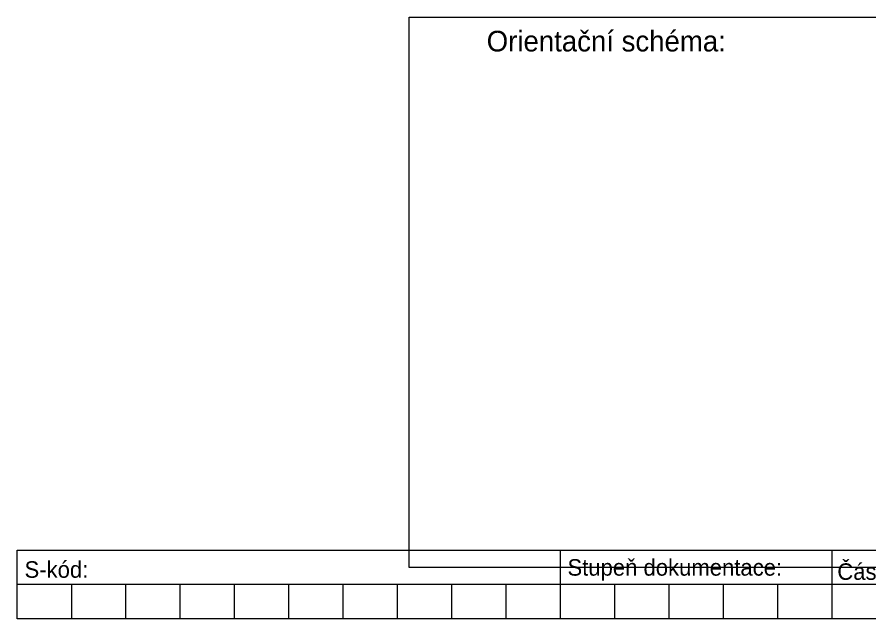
# Model space of a CAD drawing. Extents: x 3181 to 4881, y -2428 to -1984.
# Drawn here: x 3181 to 3800, y -2428 to -1991 of the extents above; entities that cross this region are included whole.
import ezdxf

# ---------------------------------------------------------------- set-up
doc = ezdxf.new("R2010")
doc.units = 0
doc.layers.add('Vrstva 2', color=7, linetype='Continuous')
doc.layers.add('Vrstva 8', color=7, linetype='Continuous')

# ---------------------------------------------------------------- blocks, each defined once
blk = doc.blocks.new('_U1')
at = {"layer": 'Vrstva 8'}
for p, q in [((-4.55, 0.25), (-4.55, -0.25)), ((-2.575, 0.25), (-2.575, -0.25)), ((-0.205, 0.25), (-0.205, -0.25)), ((3.35, 0.25), (3.35, -0.25)), ((4.535, 0.25), (4.535, -0.25)), ((6.905, 0.25), (6.905, -0.25)), ((8.5, 0), (-8.5, 0)), ((-8.105, 0), (-8.105, -0.25)), ((-7.71, 0), (-7.71, -0.25)), ((-7.315, 0), (-7.315, -0.25)), ((-6.92, 0), (-6.92, -0.25)), ((-6.525, 0), (-6.525, -0.25)), ((-6.13, 0), (-6.13, -0.25)), ((-5.735, 0), (-5.735, -0.25)), ((-5.34, 0), (-5.34, -0.25)), ((-4.945, 0), (-4.945, -0.25)), ((-4.155, 0), (-4.155, -0.25)), ((-3.76, 0), (-3.76, -0.25)), ((-3.365, 0), (-3.365, -0.25)), ((-2.97, 0), (-2.97, -0.25)), ((-2.18, 0), (-2.18, -0.25)), ((-1.785, 0), (-1.785, -0.25)), ((-1.39, 0), (-1.39, -0.25)), ((-0.995, 0), (-0.995, -0.25)), ((-0.6, 0), (-0.6, -0.25)), ((0.19, 0), (0.19, -0.25)), ((0.585, 0), (0.585, -0.25)), ((0.98, 0), (0.98, -0.25)), ((1.375, 0), (1.375, -0.25)), ((1.77, 0), (1.77, -0.25)), ((2.165, 0), (2.165, -0.25)), ((2.56, 0), (2.56, -0.25)), ((2.955, 0), (2.955, -0.25)), ((3.745, 0), (3.745, -0.25)), ((4.14, 0), (4.14, -0.25)), ((4.93, 0), (4.93, -0.25)), ((5.325, 0), (5.325, -0.25)), ((5.72, 0), (5.72, -0.25)), ((6.115, 0), (6.115, -0.25)), ((6.51, 0), (6.51, -0.25)), ((7.3, 0), (7.3, -0.25)), ((7.695, 0), (7.695, -0.25)), ((8.09, 0), (8.09, -0.25))]:
    blk.add_line(p, q, dxfattribs=at)
blk.add_lwpolyline([(-8.5, 0.25), (8.5, 0.25), (8.5, -0.25), (-8.5, -0.25)], close=True, dxfattribs=at)
for s, p in [('Stupeň dokumentace:', (-4.497, 0.0646)), ('Část:', (-2.5344, 0.0343)), ('Objekt:', (-0.1575, 0.0699)), ('Podobjekt:', (3.3643, 0.0699)), ('S-kód:', (-8.4454, 0.0493)), ('Příloha:', (4.6073, 0.0493)), ('Revize:', (6.9357, 0.0562))]:
    blk.add_text(s, height=0.12, dxfattribs=at).set_placement(p)
blk = doc.blocks.new('_U3')
at = {"layer": 'Vrstva 2'}
blk.add_lwpolyline([(-5.33255, 2.00005), (5.33245, 2.00005), (5.33245, -1.99995), (-5.33255, -1.99995)], close=True, dxfattribs=at)
blk.add_text('Orientační schéma:', height=0.15, dxfattribs=at).set_placement((-4.76755, 1.75005))

msp = doc.modelspace()

# ---------------------------------------------------------------- block references
at = {"layer": 'Vrstva 2', "xscale": 100, "yscale": 100}
msp.add_blockref('_U3', (3998.89, -2190.81), dxfattribs=at)
at = {"layer": 'Vrstva 8', "xscale": 100, "yscale": 100}
msp.add_blockref('_U1', (4030.56, -2403.31), dxfattribs=at)

doc.saveas('drawing.dxf')
